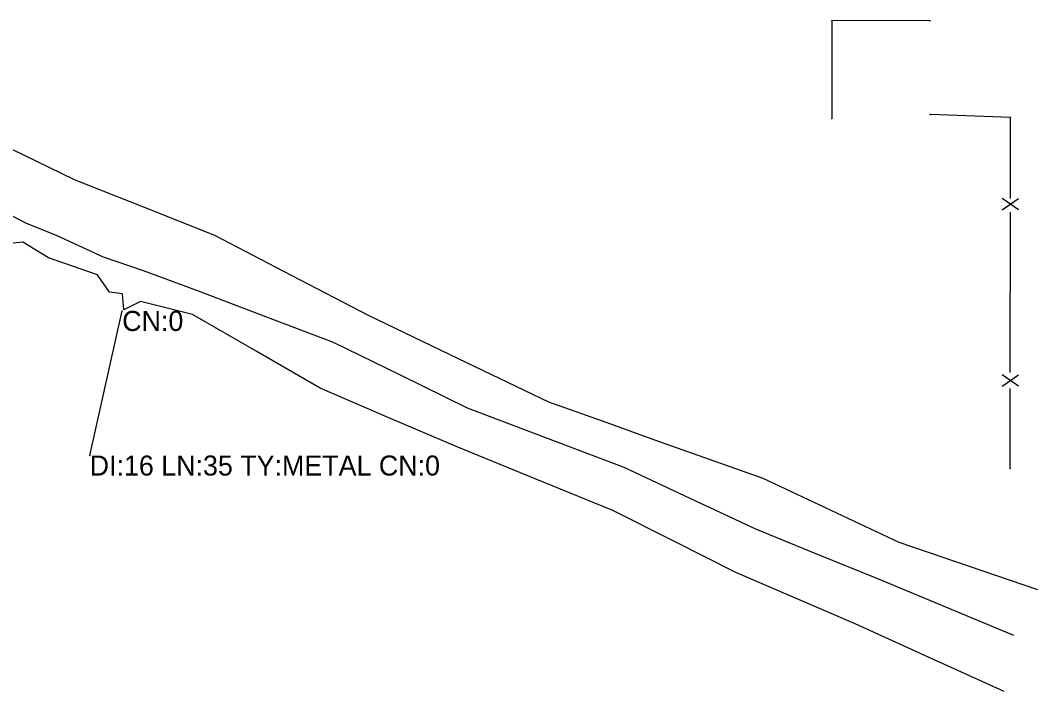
# Model space of a CAD drawing. Extents: x 1939239 to 1943096, y 531224 to 537447.
# Drawn here: x 1941349.8 to 1941603.4, y 534447 to 534614.4 of the extents above; entities that cross this region are included whole.
import ezdxf

# ---------------------------------------------------------------- set-up
doc = ezdxf.new("R2010")
doc.units = 0
for name, color, linetype in [('S_BUILDING', 7, 'Continuous'), ('S_CROSS_DRAIN', 7, 'Continuous'), ('S_CROSS_DRAIN_ANNOT', 7, 'Continuous'), ('S_DITCHLINE', 7, 'Continuous'), ('S_DRG_PT_SYM', 7, 'Continuous'), ('S_FENCE', 7, 'Continuous'), ('S_MSC_PT_SYM', 7, 'Continuous'), ('S_STR_PT_SYM', 7, 'Continuous')]:
    doc.layers.add(name, color=color, linetype=linetype)

msp = doc.modelspace()

# ---------------------------------------------------------------- linework, layer by layer
at = {"layer": 'S_BUILDING'}
for p, q in [((1941552.07, 534614.35), (1941552.01, 534589.9)), ((1941576.54, 534614.26), (1941552.07, 534614.35))]:
    msp.add_line(p, q, dxfattribs=at)
at = {"layer": 'S_CROSS_DRAIN'}
msp.add_line((1941367.04, 534505.86), (1941375.15, 534541.92), dxfattribs=at)
at = {"layer": 'S_DITCHLINE'}
for points in [[(1941341.03, 534585.44), (1941363.13, 534574.69), (1941380.64, 534567.77), (1941398.15, 534560.84), (1941417.29, 534550.86), (1941436.44, 534540.88), (1941458.92, 534530.05), (1941481.4, 534519.21), (1941494.76, 534514.47), (1941508.13, 534509.72), (1941521.49, 534504.97), (1941534.85, 534500.22), (1941551.81, 534492.22), (1941568.77, 534484.21), (1941586.06, 534478.34), (1941603.36, 534472.48)], [(1941597.39, 534460.94), (1941580.47, 534468.01), (1941563.55, 534475.08), (1941548.34, 534481.27), (1941533.12, 534487.45), (1941516.71, 534495.14), (1941500.29, 534502.83), (1941480.77, 534510.26), (1941461.26, 534517.69), (1941444.52, 534525.87), (1941427.79, 534534.06), (1941410.99, 534540.47), (1941394.19, 534546.88), (1941380.44, 534551.91), (1941370.5, 534555.3), (1941358.92, 534560.68), (1941351.14, 534563.83), (1941338.22, 534570.58)], [(1941595.01, 534446.96), (1941576.45, 534455.4), (1941557.88, 534463.84), (1941543.02, 534470.27), (1941528.15, 534476.69), (1941512.79, 534484.42), (1941497.42, 534492.16), (1941478.1, 534500.06), (1941458.78, 534507.95), (1941441.63, 534515.29), (1941424.47, 534522.63), (1941408.56, 534531.85), (1941392.65, 534541.07), (1941379.73, 534544.25), (1941375.52, 534542.16), (1941375.23, 534546.17), (1941371.97, 534546.6), (1941369.01, 534550.95), (1941356.75, 534555.14), (1941350.41, 534559.11), (1941339.34, 534557.91)]]:
    msp.add_lwpolyline(points, dxfattribs=at)
at = {"layer": 'S_DRG_PT_SYM'}
for points in [[(1941375.15, 534541.92), (1941375.15, 534541.97), (1941375.15, 534541.92), (1941375.1, 534541.92), (1941375.15, 534541.92), (1941375.15, 534541.87), (1941375.15, 534541.92), (1941375.2, 534541.92)], [(1941367.04, 534505.86), (1941367.04, 534505.91), (1941367.04, 534505.86), (1941366.99, 534505.86), (1941367.04, 534505.86), (1941367.04, 534505.81), (1941367.04, 534505.86), (1941367.09, 534505.86)]]:
    msp.add_lwpolyline(points, dxfattribs=at)
at = {"layer": 'S_FENCE'}
for p, q in [((1941598.62, 534567.11), (1941594.53, 534569.98)), ((1941598.62, 534567.11), (1941594.53, 534569.98)), ((1941594.53, 534567.11), (1941598.62, 534569.97)), ((1941594.53, 534567.11), (1941598.62, 534569.97)), ((1941594.49, 534523.13), (1941598.59, 534526)), ((1941594.49, 534523.13), (1941598.59, 534526)), ((1941598.59, 534523.13), (1941594.5, 534526)), ((1941598.59, 534523.13), (1941594.5, 534526))]:
    msp.add_line(p, q, dxfattribs=at)
for points in [[(1941596.59, 534590.13), (1941576.62, 534590.94)], [(1941596.59, 534590.13), (1941576.62, 534590.94)], [(1941596.58, 534569.98), (1941596.59, 534589.97)], [(1941596.58, 534569.98), (1941596.59, 534589.97)], [(1941596.54, 534526.56), (1941596.57, 534566.54)], [(1941596.54, 534526.56), (1941596.57, 534566.54)], [(1941596.53, 534502.58), (1941596.54, 534522.57)], [(1941596.53, 534502.58), (1941596.54, 534522.57)]]:
    msp.add_lwpolyline(points, dxfattribs=at)
at = {"layer": 'S_MSC_PT_SYM'}
for points in [[(1941576.57, 534590.94), (1941576.57, 534590.99), (1941576.57, 534590.94), (1941576.52, 534590.94), (1941576.57, 534590.94), (1941576.57, 534590.89), (1941576.57, 534590.94), (1941576.62, 534590.94)], [(1941596.59, 534590.13), (1941596.59, 534590.18), (1941596.59, 534590.13), (1941596.54, 534590.13), (1941596.59, 534590.13), (1941596.59, 534590.08), (1941596.59, 534590.13), (1941596.64, 534590.13)], [(1941596.53, 534502.58), (1941596.53, 534502.63), (1941596.53, 534502.58), (1941596.48, 534502.58), (1941596.53, 534502.58), (1941596.53, 534502.53), (1941596.53, 534502.58), (1941596.58, 534502.58)]]:
    msp.add_lwpolyline(points, dxfattribs=at)
at = {"layer": 'S_STR_PT_SYM'}
for points in [[(1941552.07, 534614.35), (1941552.07, 534614.4), (1941552.07, 534614.35), (1941552.02, 534614.35), (1941552.07, 534614.35), (1941552.07, 534614.3), (1941552.07, 534614.35), (1941552.12, 534614.35)], [(1941576.54, 534614.26), (1941576.54, 534614.31), (1941576.54, 534614.26), (1941576.49, 534614.26), (1941576.54, 534614.26), (1941576.54, 534614.2), (1941576.54, 534614.26), (1941576.59, 534614.26)], [(1941552.01, 534589.9), (1941552.01, 534589.95), (1941552.01, 534589.9), (1941551.96, 534589.9), (1941552.01, 534589.9), (1941552.01, 534589.85), (1941552.01, 534589.9), (1941552.06, 534589.9)]]:
    msp.add_lwpolyline(points, dxfattribs=at)

# ---------------------------------------------------------------- texts
at = {"layer": 'S_CROSS_DRAIN_ANNOT'}
for s, p in [('CN:0', (1941375.15, 534536.92)), ('DI:16 LN:35 TY:METAL CN:0', (1941367.04, 534500.86))]:
    msp.add_text(s, height=5, dxfattribs=at).set_placement(p)

doc.saveas('drawing.dxf')
